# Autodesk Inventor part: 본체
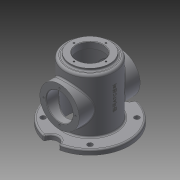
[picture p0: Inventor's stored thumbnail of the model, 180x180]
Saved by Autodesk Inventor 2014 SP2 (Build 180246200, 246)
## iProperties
Created: 2018-04
Part Number: 본체
Material: Generic
Document SubType Name: Modeling
Designer: 거성
Density: 1 g/cm^3
Appearance: Default
Author: 거성
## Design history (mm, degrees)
sketch "스케치1"
  geometry: A1 r 15 centre (80, 0) between (78.594, 14.934) and (78.594, -14.934); A2 r 15 centre (-80, 0) between (-78.594, -14.934) and (-78.594, 14.934); A3 r 80 centre (0, 0) between (-78.594, -14.934) and (78.594, -14.934); A4 r 80 centre (0, 0) between (78.594, 14.934) and (-78.594, 14.934); 1 further point
  constraints: 8 point on circle, 4 centre point, 2 horizontal alignment, 1 coincident
  dimensions: "d1" = 30 diameter of A2; "d2" = 30 diameter of A1
extrude "돌출1" new body sketch "스케치1" distance "d3" = 10; taper "d4" = 0 deg
sketch "스케치2"
  geometry: C1 r 50 at (0, 0); A1 r 80 centre (0, 0) between (78.594, 14.934) and (-78.594, 14.934) reference
  constraints: 1 centre point, 1 concentric
  dimensions: "d5" = 100 diameter of C1
extrude "돌출2" join sketch "스케치2" distance "d6" = 110; taper "d7" = 0 deg
sketch "스케치3"
  geometry: C1 r 50 at (0, 0) reference; C2 r 40 at (0, 0)
  constraints: 1 centre point, 1 concentric
  dimensions: "d8" = 80 diameter of C2
extrude "돌출3" join sketch "스케치3" distance "d9" = 5; taper "d10" = 0 deg
sketch "스케치5"
  geometry: C1 r 50 at (0, 0); A1 r 80 centre (0, 0) between (78.594, 14.934) and (-78.594, 14.934) reference
  constraints: 1 centre point, 1 concentric
  dimensions: "d15" = 100 diameter of C1
extrude "돌출5" join sketch "스케치5" distance "d16" = 8; taper "d17" = 0 deg
sketch "스케치6" dims "d18" = 135
  geometry: L1 (0, 0)-(-75.007, 75.007); L2 (0, 0)-(-110.102, 0); A1 r 80 centre (0, 0) between (78.594, 14.934) and (-78.594, 14.934) reference; 1 further point
  constraints: 4 end point, 1 horizontal, 1 point on line, 4 other
  dimensions: "d19" = 45 deg angle of L2 L1
hole "구멍1" sketch "스케치6" at (-47.73, 47.73) diameter "d20" = 10; stored, may be unused: countersink angle "d24" = 90 deg, drill point angle "d26" = 118 deg; dims "d21" = 6, "d22" = 4, "d23" = 2, "d25" = 8
sketch "스케치7"
  geometry: C1 r 40 at (60, 0); 1 further point
  constraints: 1 centre point, 1 horizontal alignment
  dimensions: "d30" = 60 distance of C1.centre point (0, 0); "d31" = 80 diameter of C1
extrude "돌출6" join sketch "스케치7" stored distance "d32" = 124; taper "d33" = 0 deg
hole "구멍2" diameter "d36" = 54; stored, may be unused: countersink angle "d40" = 90 deg, drill point angle "d42" = 118 deg; dims "d34" = 10, "d35" = 10, "d37" = 6, "d38" = 4, "d39" = 2, "d41" = 8
hole "구멍3" diameter "d45" = 54; stored, may be unused: countersink angle "d49" = 90 deg, drill point angle "d51" = 0 deg; dims "d43" = 10, "d44" = 10, "d46" = 6, "d47" = 4, "d48" = 2, "d50" = 13
hole "구멍4" diameter "d54" = 90; stored, may be unused: countersink angle "d58" = 90 deg, drill point angle "d60" = 0 deg; dims "d52" = 10, "d53" = 10, "d55" = 6, "d56" = 4, "d57" = 2, "d59" = 120
sketch "스케치8" dims "d61" = 65
  geometry: C1 r 27 at (0, 0) reference; C2 r 40 at (0, 0) reference; 2 further points
  constraints: 2 vertical alignment, 3 other
hole "구멍5" sketch "스케치8" at (0, 32.5) diameter "d62" = 3.242; stored, may be unused: countersink angle "d66" = 90 deg, drill point angle "d68" = 118 deg; dims "d63" = 8, "d64" = 4, "d65" = 2, "d67" = 10
sketch "스케치9" dims "d72" = 65
  geometry: C1 r 27 at (0, 0) reference; C2 r 40 at (0, 0) reference; 3 further points
  constraints: 2 vertical alignment, 3 other
hole "구멍6" sketch "스케치9" at (0, 32.5) diameter "d73" = 3.242; stored, may be unused: countersink angle "d77" = 90 deg, drill point angle "d79" = 118 deg; dims "d74" = 8, "d75" = 4, "d76" = 2, "d78" = 10
sketch "스케치10"
  geometry: C1 r 40 at (0, 0) reference; C2 r 32.5 at (0, 0); C3 r 1.621 at (0, 32.5) reference; 2 further points
  constraints: 1 centre point, 1 coincident, 1 concentric
  dimensions: "d83" = 65 diameter of C2
hole "구멍7" sketch "스케치10" at (0, 32.5) diameter "d84" = 3.242; stored, may be unused: countersink angle "d88" = 90 deg, drill point angle "d90" = 118 deg; dims "d85" = 8, "d86" = 4, "d87" = 2, "d89" = 10
fillet "모깎기1" dims "d94" = 5
fillet "모깎기2" dims "d95" = 3
fillet "모깎기3" dims "d96" = 3
chamfer "모따기1" distance "d97" = 1; stored, may be unused: second distance "d98" = 2, angle "d99" = 45 deg
node "작업 평면1"
sketch "스케치11"
  geometry: L1 (-3.5, 46)-(-3.5, 94); L2 (-3.5, 94)-(3.5, 94); L3 (3.5, 94)-(3.5, 46); L4 (3.5, 46)-(-3.5, 46); L5 (0, 46)-(0, 94); L6 (-3.5, 70)-(3.5, 70); 1 further point
  constraints: 4 end point, 4 midpoint, 1 vertical alignment, 2 other
  dimensions: "d101" = 7 distance between parallel lines of L3 L1; "d102" = 48 distance between parallel lines of L2 L4; "d103" = 70 distance from line of L6 point (0, 0)
feature "엠보싱1" sketch "스케치11" dims "d1" = 30, "d2" = 30, "d104" = 0.5, "d105" = 0
chamfer "모따기3" distance "d109" = 1; stored, may be unused: second distance "d110" = 2, angle "d111" = 45 deg
node "솔리드1"
pattern_circular "원형 패턴1" dims angle "d28" = 360 deg
pattern_circular "원형 패턴2" dims angle "d70" = 360 deg
pattern_circular "원형 패턴3" dims angle "d81" = 360 deg
pattern_circular "원형 패턴4" dims angle "d92" = 360 deg
other parameters: "d100" = -92.075
